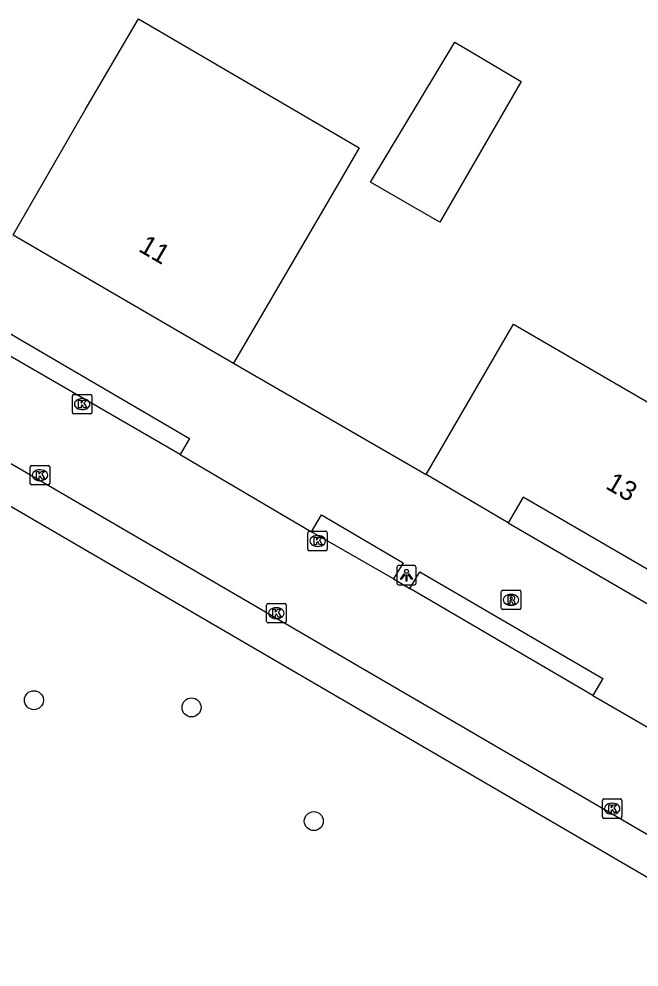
# Model space of a CAD drawing. Extents: x 156502 to 159074, y 384229 to 386094.
# Drawn here: x 157142.73 to 157174.65, y 385868.93 to 385917.72 of the extents above; entities that cross this region are included whole.
import ezdxf

# ---------------------------------------------------------------- set-up
doc = ezdxf.new("R2010")
doc.units = 0
for name, color, linetype in [('IMGEO_Boom', 7, 'Continuous'), ('IMGEO_Hek', 7, 'Continuous'), ('IMGEO_Kolk', 7, 'Continuous'), ('IMGEO_Lichtpunt', 7, 'Continuous'), ('IMGEO_Pand', 7, 'Continuous'), ('IMGEO_Pand_nummerreeks', 7, 'Continuous'), ('IMGEO_Parkeervlak_open', 7, 'Continuous'), ('IMGEO_Rijbaan_lokaal_open', 7, 'Continuous'), ('IMGEO_Rioolput', 7, 'Continuous'), ('IMGEO_Voetpad_open', 7, 'Continuous')]:
    doc.layers.add(name, color=color, linetype=linetype)

msp = doc.modelspace()

# ---------------------------------------------------------------- linework, layer by layer
at = {"layer": 'IMGEO_Boom'}
for centre in [(157143.505, 385882.66), (157151.614, 385882.288), (157157.909, 385876.436)]:
    msp.add_circle(centre, 0.489, dxfattribs=at)
at = {"layer": 'IMGEO_Hek'}
for points in [[(157153.769, 385900.007), (157163.686, 385894.272)], [(157167.911, 385891.794), (157185.093, 385881.809)]]:
    msp.add_lwpolyline(points, dxfattribs=at)
at = {"layer": 'IMGEO_Kolk'}
for p, q in [((157145.485, 385897.473), (157145.485, 385898.325)), ((157145.56, 385898.399), (157146.412, 385898.399)), ((157146.486, 385898.325), (157146.486, 385897.473)), ((157145.973, 385898.179), (157145.998, 385898.179)), ((157146.412, 385897.399), (157145.56, 385897.399)), ((157145.996, 385897.619), (157145.971, 385897.619)), ((157143.314, 385893.811), (157143.314, 385894.663)), ((157143.389, 385894.737), (157144.241, 385894.737)), ((157143.802, 385894.517), (157143.827, 385894.517)), ((157144.315, 385894.663), (157144.315, 385893.811)), ((157143.825, 385893.957), (157143.8, 385893.957)), ((157144.241, 385893.737), (157143.389, 385893.737)), ((157157.601, 385890.429), (157157.601, 385891.281)), ((157157.676, 385891.355), (157158.528, 385891.355)), ((157158.089, 385891.135), (157158.114, 385891.135)), ((157158.602, 385891.281), (157158.602, 385890.429)), ((157158.112, 385890.575), (157158.087, 385890.575)), ((157158.528, 385890.355), (157157.676, 385890.355)), ((157155.557, 385887.64), (157156.409, 385887.64)), ((157155.482, 385886.714), (157155.482, 385887.566)), ((157155.97, 385887.42), (157155.995, 385887.42)), ((157156.483, 385887.566), (157156.483, 385886.714)), ((157156.409, 385886.64), (157155.557, 385886.64)), ((157155.993, 385886.86), (157155.968, 385886.86)), ((157172.764, 385876.65), (157172.764, 385877.502)), ((157172.839, 385877.576), (157173.691, 385877.576)), ((157173.252, 385877.356), (157173.277, 385877.356)), ((157173.765, 385877.502), (157173.765, 385876.65)), ((157173.691, 385876.576), (157172.839, 385876.576)), ((157173.275, 385876.796), (157173.25, 385876.796))]:
    msp.add_line(p, q, dxfattribs=at)
for points in [[(157145.485, 385897.473), (157145.485, 385898.325)], [(157145.56, 385898.399), (157146.412, 385898.399)], [(157146.486, 385898.325), (157146.486, 385897.473)], [(157145.806, 385898.099), (157145.929, 385898.099), (157145.929, 385897.948), (157146.059, 385898.099), (157146.223, 385898.099), (157146.077, 385897.948), (157146.23, 385897.699), (157146.078, 385897.699), (157145.993, 385897.863), (157145.929, 385897.796), (157145.929, 385897.699), (157145.806, 385897.699), (157145.806, 385898.099)], [(157146.412, 385897.399), (157145.56, 385897.399)], [(157143.314, 385893.811), (157143.314, 385894.663)], [(157143.389, 385894.737), (157144.241, 385894.737)], [(157143.635, 385894.437), (157143.758, 385894.437), (157143.758, 385894.286), (157143.888, 385894.437), (157144.052, 385894.437), (157143.906, 385894.286), (157144.059, 385894.037), (157143.907, 385894.037), (157143.822, 385894.201), (157143.758, 385894.134), (157143.758, 385894.037), (157143.635, 385894.037), (157143.635, 385894.437)], [(157144.315, 385894.663), (157144.315, 385893.811)], [(157144.241, 385893.737), (157143.389, 385893.737)], [(157157.601, 385890.429), (157157.601, 385891.281)], [(157157.676, 385891.355), (157158.528, 385891.355)], [(157157.922, 385891.055), (157158.045, 385891.055), (157158.045, 385890.904), (157158.175, 385891.055), (157158.339, 385891.055), (157158.193, 385890.904), (157158.346, 385890.655), (157158.194, 385890.655), (157158.109, 385890.819), (157158.045, 385890.752), (157158.045, 385890.655), (157157.922, 385890.655), (157157.922, 385891.055)], [(157158.602, 385891.281), (157158.602, 385890.429)], [(157158.528, 385890.355), (157157.676, 385890.355)], [(157155.557, 385887.64), (157156.409, 385887.64)], [(157155.482, 385886.714), (157155.482, 385887.566)], [(157155.803, 385887.34), (157155.926, 385887.34), (157155.926, 385887.189), (157156.056, 385887.34), (157156.22, 385887.34), (157156.074, 385887.189), (157156.227, 385886.94), (157156.075, 385886.94), (157155.99, 385887.104), (157155.926, 385887.037), (157155.926, 385886.94), (157155.803, 385886.94), (157155.803, 385887.34)], [(157156.483, 385887.566), (157156.483, 385886.714)], [(157156.409, 385886.64), (157155.557, 385886.64)], [(157172.764, 385876.65), (157172.764, 385877.502)], [(157172.839, 385877.576), (157173.691, 385877.576)], [(157173.765, 385877.502), (157173.765, 385876.65)], [(157173.085, 385877.276), (157173.208, 385877.276), (157173.208, 385877.125), (157173.338, 385877.276), (157173.502, 385877.276), (157173.356, 385877.125), (157173.509, 385876.876), (157173.357, 385876.876), (157173.272, 385877.04), (157173.208, 385876.973), (157173.208, 385876.876), (157173.085, 385876.876), (157173.085, 385877.276)], [(157173.691, 385876.576), (157172.839, 385876.576)]]:
    msp.add_lwpolyline(points, dxfattribs=at)
for centre, start, end in [((157145.562, 385898.323), 91.552, 178.448), ((157145.562, 385898.323), 91.552, 178.448), ((157146.41, 385898.323), 1.552, 88.448), ((157146.41, 385898.323), 1.552, 88.448), ((157145.562, 385897.475), 181.552, 268.448), ((157145.562, 385897.475), 181.552, 268.448), ((157146.41, 385897.475), 271.552, 358.448), ((157146.41, 385897.475), 271.552, 358.448), ((157143.391, 385894.661), 91.552, 178.448), ((157143.391, 385894.661), 91.552, 178.448), ((157144.239, 385894.661), 1.552, 88.448), ((157144.239, 385894.661), 1.552, 88.448), ((157143.391, 385893.813), 181.552, 268.448), ((157143.391, 385893.813), 181.552, 268.448), ((157144.239, 385893.813), 271.552, 358.448), ((157144.239, 385893.813), 271.552, 358.448), ((157157.678, 385891.279), 91.552, 178.448), ((157157.678, 385891.279), 91.552, 178.448), ((157158.526, 385891.279), 1.552, 88.448), ((157158.526, 385891.279), 1.552, 88.448), ((157157.678, 385890.431), 181.552, 268.448), ((157157.678, 385890.431), 181.552, 268.448), ((157158.526, 385890.431), 271.552, 358.448), ((157158.526, 385890.431), 271.552, 358.448), ((157155.559, 385887.564), 91.552, 178.448), ((157155.559, 385887.564), 91.552, 178.448), ((157156.407, 385887.564), 1.552, 88.448), ((157156.407, 385887.564), 1.552, 88.448), ((157155.559, 385886.716), 181.552, 268.448), ((157155.559, 385886.716), 181.552, 268.448), ((157156.407, 385886.716), 271.552, 358.448), ((157156.407, 385886.716), 271.552, 358.448), ((157172.841, 385877.5), 91.552, 178.448), ((157172.841, 385877.5), 91.552, 178.448), ((157173.689, 385877.5), 1.552, 88.448), ((157173.689, 385877.5), 1.552, 88.448), ((157172.841, 385876.652), 181.552, 268.448), ((157172.841, 385876.652), 181.552, 268.448), ((157173.689, 385876.652), 271.552, 358.448), ((157173.689, 385876.652), 271.552, 358.448)]:
    msp.add_arc(centre, 0.0765, start, end, dxfattribs=at)
for centre, major_axis, ratio, start_param, end_param in [((157145.972, 385897.899), (-0.387, 0.002), 0.722429, 4.712389, 7.853982), ((157145.997, 385897.899), (-0.39, 0.002), 0.717154, 1.570796, 4.712389), ((157143.801, 385894.237), (-0.387, 0.002), 0.722429, 4.712389, 7.853982), ((157143.826, 385894.237), (-0.39, 0.002), 0.717154, 1.570796, 4.712389), ((157158.088, 385890.855), (-0.387, 0.002), 0.722429, 4.712389, 7.853982), ((157158.113, 385890.855), (-0.39, 0.002), 0.717154, 1.570796, 4.712389), ((157155.969, 385887.14), (-0.387, 0.002), 0.722429, 4.712389, 7.853982), ((157155.994, 385887.14), (-0.39, 0.002), 0.717154, 1.570796, 4.712389), ((157173.251, 385877.076), (-0.387, 0.002), 0.722429, 4.712389, 7.853982), ((157173.276, 385877.076), (-0.39, 0.002), 0.717154, 1.570796, 4.712389)]:
    msp.add_ellipse(centre, major_axis=major_axis, ratio=ratio, start_param=start_param, end_param=end_param, dxfattribs=at)
at = {"layer": 'IMGEO_Lichtpunt'}
for p, q in [((157163.083, 385889.59), (157162.275, 385889.59)), ((157163.083, 385889.59), (157162.275, 385889.59)), ((157162.181, 385889.495), (157162.181, 385888.688)), ((157162.181, 385889.495), (157162.181, 385888.688)), ((157163.177, 385888.688), (157163.177, 385889.495)), ((157163.177, 385888.688), (157163.177, 385889.495)), ((157162.275, 385888.594), (157163.083, 385888.594)), ((157162.275, 385888.594), (157163.083, 385888.594))]:
    msp.add_line(p, q, dxfattribs=at)
for points in [[(157162.555, 385889.159), (157162.594, 385889.131), (157162.406, 385888.869), (157162.368, 385888.896), (157162.555, 385889.159)], [(157162.657, 385889.111), (157162.704, 385889.111), (157162.704, 385888.789), (157162.657, 385888.789), (157162.657, 385889.111)], [(157162.767, 385889.131), (157162.805, 385889.158), (157162.992, 385888.896), (157162.953, 385888.868), (157162.767, 385889.131)]]:
    msp.add_lwpolyline(points, dxfattribs=at)
msp.add_circle((157162.68, 385889.293), 0.0994, dxfattribs=at)
for centre, start, end in [((157162.275, 385889.495), 90, 180), ((157162.275, 385889.495), 90, 180), ((157163.083, 385889.495), 0, 90), ((157163.083, 385889.495), 0, 90), ((157162.275, 385888.688), 180, 270), ((157162.275, 385888.688), 180, 270), ((157163.083, 385888.688), 270, 0), ((157163.083, 385888.688), 270, 360)]:
    msp.add_arc(centre, 0.0946, start, end, dxfattribs=at)
at = {"layer": 'IMGEO_Pand'}
for points in [[(157142.433, 385906.61), (157146.148, 385913.037), (157148.886, 385917.721), (157160.243, 385911.082), (157159, 385908.955), (157153.769, 385900.007)], [(157164.388, 385907.266), (157160.82, 385909.313), (157165.166, 385916.522), (157168.575, 385914.494), (157164.388, 385907.266)], [(157142.433, 385906.61), (157153.769, 385900.007)], [(157163.686, 385894.272), (157168.192, 385902.015), (157177.313, 385896.706), (157177.822, 385897.585), (157177.527, 385897.755), (157180.877, 385903.546), (157188.204, 385899.308), (157184.874, 385893.54), (157179.785, 385896.459), (157179.286, 385895.561), (157179.562, 385895.399), (157175.806, 385888.97), (157168.68, 385893.106), (157167.911, 385891.794)], [(157167.911, 385891.794), (157163.686, 385894.272)]]:
    msp.add_lwpolyline(points, dxfattribs=at)
at = {"layer": 'IMGEO_Parkeervlak_open'}
msp.add_lwpolyline([(157138.908, 385894.614), (157192.564, 385863.354)], dxfattribs=at)
at = {"layer": 'IMGEO_Rijbaan_lokaal_open'}
for points in [[(157151.032, 385895.3), (157141.609, 385900.746)], [(157139.856, 385896.261), (157193.373, 385865.1)], [(157151.032, 385895.3), (157157.792, 385891.329)], [(157162.018, 385888.901), (157157.792, 385891.329)], [(157162.018, 385888.901), (157162.851, 385888.415)], [(157172.275, 385882.9), (157162.851, 385888.415)], [(157172.275, 385882.9), (157179.189, 385878.901)]]:
    msp.add_lwpolyline(points, dxfattribs=at)
at = {"layer": 'IMGEO_Rioolput'}
for p, q in [((157167.559, 385887.399), (157167.559, 385888.251)), ((157167.634, 385888.325), (157168.486, 385888.325)), ((157168.047, 385888.105), (157168.072, 385888.105)), ((157168.56, 385888.251), (157168.56, 385887.399)), ((157168.486, 385887.325), (157167.634, 385887.325)), ((157168.07, 385887.545), (157168.045, 385887.545))]:
    msp.add_line(p, q, dxfattribs=at)
for points in [[(157167.559, 385887.399), (157167.559, 385888.251)], [(157167.634, 385888.325), (157168.486, 385888.325)], [(157168.56, 385888.251), (157168.56, 385887.399)], [(157168.148, 385888.023), (157167.896, 385888.025), (157167.896, 385887.625)], [(157167.896, 385887.625), (157168.02, 385887.625), (157168.02, 385887.787), (157168.031, 385887.787)], [(157168.074, 385887.944), (157168.02, 385887.944), (157168.02, 385887.863)], [(157168.02, 385887.863), (157168.072, 385887.863)], [(157168.078, 385887.758), (157168.149, 385887.625), (157168.289, 385887.625), (157168.224, 385887.751)], [(157168.486, 385887.325), (157167.634, 385887.325)]]:
    msp.add_lwpolyline(points, dxfattribs=at)
for centre, radius, start, end in [((157167.636, 385888.249), 0.0765, 91.552, 178.448), ((157167.636, 385888.249), 0.0765, 91.552, 178.448), ((157168.484, 385888.249), 0.0765, 1.552, 88.448), ((157168.484, 385888.249), 0.0765, 1.552, 88.448), ((157168.03, 385887.734), 0.0533, 26.0293, 88.6989), ((157168.056, 385888.052), 0.19, 274.7715, 282.9687), ((157168.08, 385887.848), 0.0964, 77.0061, 93.1865), ((157168.094, 385887.905), 0.0378, 276.6634, 79.6772), ((157168.147, 385887.913), 0.109, 350.3612, 89.416), ((157168.145, 385887.913), 0.112, 277.5842, 350.9817), ((157168.129, 385887.698), 0.108, 29.5134, 73.7905), ((157167.636, 385887.401), 0.0765, 181.552, 268.448), ((157167.636, 385887.401), 0.0765, 181.552, 268.448), ((157168.484, 385887.401), 0.0765, 271.552, 358.448), ((157168.484, 385887.401), 0.0765, 271.552, 358.448)]:
    msp.add_arc(centre, radius, start, end, dxfattribs=at)
for centre, major_axis, ratio, start_param, end_param in [((157168.046, 385887.825), (-0.387, 0.002), 0.722429, 4.712389, 7.853982), ((157168.071, 385887.825), (-0.39, 0.002), 0.717154, 1.570796, 4.712389)]:
    msp.add_ellipse(centre, major_axis=major_axis, ratio=ratio, start_param=start_param, end_param=end_param, dxfattribs=at)
at = {"layer": 'IMGEO_Voetpad_open'}
for points in [[(157141.609, 385900.746), (157142.124, 385901.615), (157151.51, 385896.134), (157151.032, 385895.3)], [(157153.769, 385900.007), (157163.686, 385894.272)], [(157157.792, 385891.329), (157158.298, 385892.2), (157162.501, 385889.733), (157162.018, 385888.901)], [(157167.911, 385891.794), (157185.093, 385881.809)], [(157162.851, 385888.415), (157163.363, 385889.258), (157172.777, 385883.778), (157172.275, 385882.9)]]:
    msp.add_lwpolyline(points, dxfattribs=at)

# ---------------------------------------------------------------- texts
at = {"layer": 'IMGEO_Pand_nummerreeks'}
for s, rotation, p in [('11', 329.7765, (157148.832, 385905.799)), ('13', 329.8687, (157172.874, 385893.585))]:
    msp.add_text(s, height=1, rotation=rotation, dxfattribs=at).set_placement(p)

doc.saveas('drawing.dxf')
